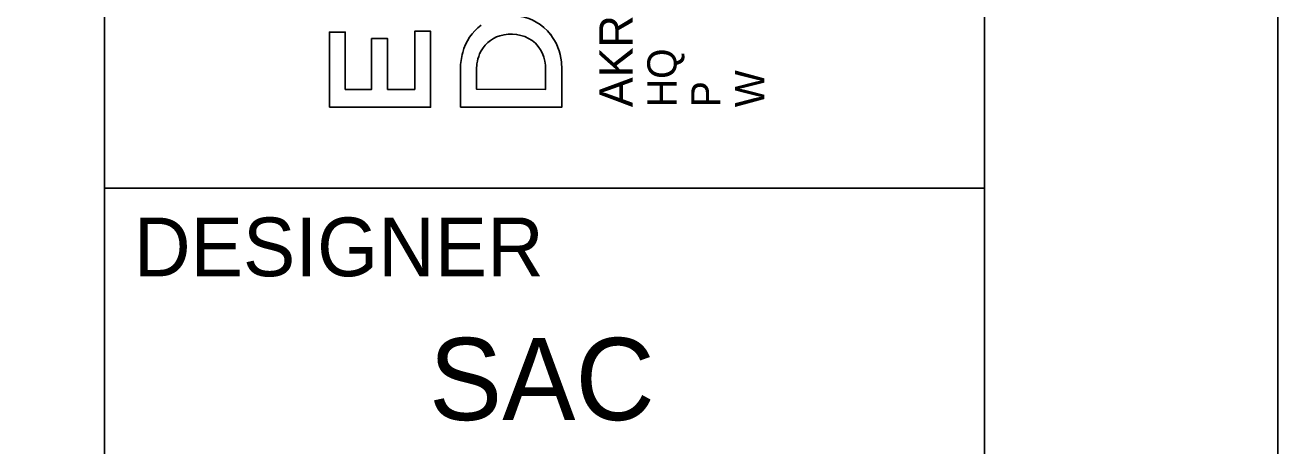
# Model space of a CAD drawing. Extents: x -0.2 to 34, y 0 to 22.
# Drawn here: x 31.864 to 34, y 2.061 to 2.778 of the extents above; entities that cross this region are included whole.
import ezdxf

# ---------------------------------------------------------------- set-up
doc = ezdxf.new("R2010")
doc.units = 0
for name, color, linetype in [('SH_Border', 7, 'Continuous'), ('SH_Cut_Line', 7, 'Continuous'), ('SH_Data', 7, 'Continuous')]:
    doc.layers.add(name, color=color, linetype=linetype)

msp = doc.modelspace()

# ---------------------------------------------------------------- linework, layer by layer
at = {"layer": 'SH_Border'}
for p, q in [((32, 0.5), (32, 21.5)), ((32, 2.5), (33.5, 2.5))]:
    msp.add_line(p, q, dxfattribs=at)
msp.add_lwpolyline([(1.5, 21.5), (33.5, 21.5), (33.5, 0.5), (1.5, 0.5)], close=True, dxfattribs=at)
at = {"layer": 'SH_Cut_Line'}
msp.add_lwpolyline([(0, 0), (34, 0), (34, 22), (0, 22)], close=True, dxfattribs=at)
at = {"layer": 'SH_Data'}
for p, q in [((32.383, 2.6379), (32.383, 2.766)), ((32.383, 2.766), (32.4101, 2.766)), ((32.4101, 2.766), (32.4101, 2.6683)), ((32.5286, 2.6683), (32.5286, 2.7672)), ((32.5286, 2.7672), (32.5557, 2.7672)), ((32.5557, 2.7672), (32.5557, 2.6379)), ((32.455, 2.6683), (32.455, 2.7549)), ((32.455, 2.7549), (32.4822, 2.7549)), ((32.4822, 2.7549), (32.4822, 2.6683)), ((32.7785, 2.715), (32.7792, 2.7021)), ((32.6064, 2.638), (32.6064, 2.704)), ((32.6347, 2.7118), (32.6341, 2.7023)), ((32.6341, 2.7023), (32.6341, 2.6684)), ((32.7515, 2.6683), (32.7515, 2.7024)), ((32.7792, 2.7021), (32.7792, 2.638)), ((32.4101, 2.6683), (32.455, 2.6683)), ((32.4822, 2.6683), (32.5286, 2.6683)), ((32.6341, 2.6684), (32.7515, 2.6683)), ((32.5557, 2.6379), (32.383, 2.6379)), ((32.7792, 2.638), (32.6064, 2.638))]:
    msp.add_line(p, q, dxfattribs=at)
msp.add_lwpolyline([(32.383, 2.6379), (32.383, 2.766), (32.4101, 2.766), (32.4101, 2.6683), (32.455, 2.6683), (32.455, 2.7549), (32.4822, 2.7549), (32.4822, 2.6683), (32.5286, 2.6683), (32.5286, 2.7672), (32.5557, 2.7672), (32.5557, 2.6379)], close=True, dxfattribs=at)
for points in [[(32.7785, 2.715), (32.7792, 2.7021), (32.7792, 2.638), (32.6064, 2.638)], [(32.6064, 2.638), (32.6064, 2.704)], [(32.6347, 2.7118), (32.6341, 2.7023), (32.6341, 2.6684), (32.7515, 2.6683), (32.7515, 2.7024)]]:
    msp.add_lwpolyline(points, dxfattribs=at)
for centre, radius, start, end in [((32.6939, 2.7089), 0.0865, 127.2362, 165.148), ((32.6939, 2.7089), 0.0865, 127.2362, 165.148), ((32.6946, 2.7113), 0.0827, 37.8521, 82.402), ((32.6946, 2.7113), 0.0827, 37.8521, 82.402), ((32.6889, 2.7078), 0.054, 106.1881, 157.3861), ((32.6889, 2.7078), 0.054, 106.1881, 157.3861), ((32.6928, 2.6986), 0.0639, 55.6727, 107.2093), ((32.6928, 2.6986), 0.0639, 55.6727, 107.2093), ((32.6859, 2.7057), 0.0931, 5.7333, 37.304), ((32.6859, 2.7057), 0.0931, 5.7333, 37.304), ((32.6929, 2.705), 0.0587, 357.4662, 52.2665), ((32.6929, 2.705), 0.0587, 357.4662, 52.2665), ((32.7143, 2.7028), 0.1078, 164.7861, 179.3704), ((32.7143, 2.7028), 0.1078, 164.7861, 179.3704), ((32.6983, 2.7039), 0.0641, 157.3571, 172.9275), ((32.6983, 2.7039), 0.0641, 157.3571, 172.9275)]:
    msp.add_arc(centre, radius, start, end, dxfattribs=at)

# ---------------------------------------------------------------- texts
for s, height, p in [('AKRON / CLEVELAND / COLUMBUS', 0.056969, (32.9001, 2.638)), ('HQ ', 0.04985, (32.9749, 2.638)), ('W', 0.0498, (33.1244, 2.638)), ('P', 0.0498, (33.0497, 2.638))]:
    msp.add_text(s, height=height, rotation=90, dxfattribs=at).set_placement(p)
for s, height, p in [('DESIGNER', 0.1, (32.05, 2.35)), ('SAC', 0.14, (32.5528, 2.105))]:
    msp.add_text(s, height=height, dxfattribs=at).set_placement(p)

doc.saveas('drawing.dxf')
